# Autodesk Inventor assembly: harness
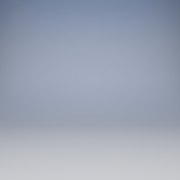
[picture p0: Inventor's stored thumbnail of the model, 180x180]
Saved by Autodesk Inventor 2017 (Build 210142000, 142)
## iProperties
HarnessSettings: <HarnessSettings><Defaults><Segments><Diameter value="0.200 in" fromwires="True"/><Offset value="0.100 in"/><ColorStyle value="Blue"/><BendRadius value="19" fro
Control State: 0
Master: False
Checked Out: False
Part Number: harness
Document SubType Name: Assembly
Shininess: 64.0
Length Units: 11272
Angle Units: 11279
Time Units: 11290
Mass Units: 11286
Length Display Precision: 3
Angle Display Precision: 2
Compacted: True
Density: 0.0
Volumn: 0.0
Area: 0.0
PropertySet Name: Model Information
HarnessSettings: <HarnessSettings><Defaults><Segments><Diameter value="0.200 in" fromwires="True"/><Offset value="0.100 in"/><ColorStyle value="Niebieska — farba ścienna — lśnią
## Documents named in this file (1)
- C:\Users\pl\Desktop\harness.iam
